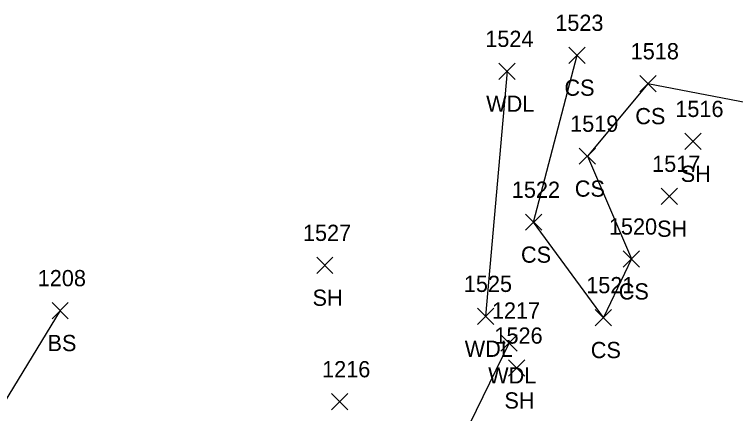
# Model space of a CAD drawing. Extents: x 1761340 to 1763889, y 696770 to 706023.
# Drawn here: x 1761564.7 to 1761653.6, y 700918.1 to 700967.3 of the extents above; entities that cross this region are included whole.
import ezdxf

# ---------------------------------------------------------------- set-up
doc = ezdxf.new("R2010")
doc.units = 0
for name, color, linetype in [('L_A', 7, 'Continuous'), ('L_I', 7, 'Continuous'), ('L_TIC', 7, 'Continuous'), ('LAWA', 7, 'Continuous'), ('LELB', 7, 'Continuous')]:
    doc.layers.add(name, color=color, linetype=linetype)

msp = doc.modelspace()

# ---------------------------------------------------------------- linework, layer by layer
at = {"layer": 'L_TIC'}
for points in [[(1761633.084, 700961.312), (1761635.084, 700963.312)], [(1761635.084, 700961.312), (1761633.084, 700963.312)], [(1761624.451, 700959.336), (1761626.451, 700961.336)], [(1761626.451, 700959.336), (1761624.451, 700961.336)], [(1761641.829, 700957.807), (1761643.829, 700959.807)], [(1761643.829, 700957.807), (1761641.829, 700959.807)], [(1761647.387, 700950.698), (1761649.387, 700952.698)], [(1761649.387, 700950.698), (1761647.387, 700952.698)], [(1761634.365, 700948.874), (1761636.365, 700950.874)], [(1761636.365, 700948.874), (1761634.365, 700950.874)], [(1761644.472, 700943.929), (1761646.472, 700945.929)], [(1761646.472, 700943.929), (1761644.472, 700945.929)], [(1761627.724, 700940.732), (1761629.724, 700942.732)], [(1761629.724, 700940.732), (1761627.724, 700942.732)], [(1761639.788, 700936.199), (1761641.788, 700938.199)], [(1761641.788, 700936.199), (1761639.788, 700938.199)], [(1761601.953, 700935.42), (1761603.953, 700937.42)], [(1761603.953, 700935.42), (1761601.953, 700937.42)], [(1761569.303, 700929.836), (1761571.303, 700931.836)], [(1761571.303, 700929.836), (1761569.303, 700931.836)], [(1761621.803, 700929.13), (1761623.803, 700931.13)], [(1761623.803, 700929.13), (1761621.803, 700931.13)], [(1761636.337, 700928.972), (1761638.337, 700930.972)], [(1761638.337, 700928.972), (1761636.337, 700930.972)], [(1761624.698, 700925.846), (1761626.698, 700927.846)], [(1761626.698, 700925.846), (1761624.698, 700927.846)], [(1761625.634, 700922.757), (1761627.634, 700924.757)], [(1761627.634, 700922.757), (1761625.634, 700924.757)], [(1761603.802, 700918.607), (1761605.802, 700920.607)], [(1761605.802, 700918.607), (1761603.802, 700920.607)]]:
    msp.add_lwpolyline(points, dxfattribs=at)
at = {"layer": 'LAWA'}
for points in [[(1761625.451, 700960.336), (1761622.803, 700930.13)], [(1761625.698, 700926.846), (1761615.117, 700905.197), (1761609.669, 700894.734), (1761609.132, 700892.975), (1761607.884, 700887.554), (1761605.527, 700886.179)]]:
    msp.add_lwpolyline(points, dxfattribs=at)
at = {"layer": 'LELB'}
for points in [[(1761657.174, 700956.034), (1761642.829, 700958.807), (1761635.365, 700949.874), (1761640.788, 700937.199), (1761637.337, 700929.972), (1761628.724, 700941.732), (1761634.084, 700962.312)], [(1761570.303, 700930.836), (1761558.728, 700911.937)]]:
    msp.add_lwpolyline(points, dxfattribs=at)

# ---------------------------------------------------------------- texts
at = {"layer": 'L_A'}
for s, p in [('CS', (1761632.525, 700957.312)), ('WDL', (1761622.868, 700955.336)), ('CS', (1761641.27, 700953.807)), ('SH', (1761646.876, 700946.698)), ('CS', (1761633.806, 700944.874)), ('SH', (1761643.96, 700939.929)), ('CS', (1761627.165, 700936.732)), ('CS', (1761639.229, 700932.199)), ('SH', (1761601.441, 700931.42)), ('BS', (1761568.744, 700925.836)), ('WDL', (1761620.22, 700925.13)), ('CS', (1761635.778, 700924.972)), ('WDL', (1761623.116, 700921.846)), ('SH', (1761625.122, 700918.757))]:
    msp.add_text(s, height=2, dxfattribs=at).set_placement(p)
at = {"layer": 'L_I'}
for s, p in [('1523', (1761631.392, 700965.312)), ('1524', (1761622.758, 700963.336)), ('1518', (1761640.703, 700961.807)), ('1516', (1761646.207, 700954.698)), ('1519', (1761633.231, 700952.874)), ('1517', (1761643.346, 700947.929)), ('1522', (1761626.032, 700944.732)), ('1520', (1761638.009, 700940.199)), ('1527', (1761600.26, 700939.42)), ('1208', (1761567.532, 700933.836)), ('1525', (1761620.11, 700933.13)), ('1521', (1761635.211, 700932.972)), ('1217', (1761623.573, 700929.846)), ('1526', (1761623.886, 700926.757)), ('1216', (1761602.622, 700922.607))]:
    msp.add_text(s, height=2, dxfattribs=at).set_placement(p)

doc.saveas('drawing.dxf')
